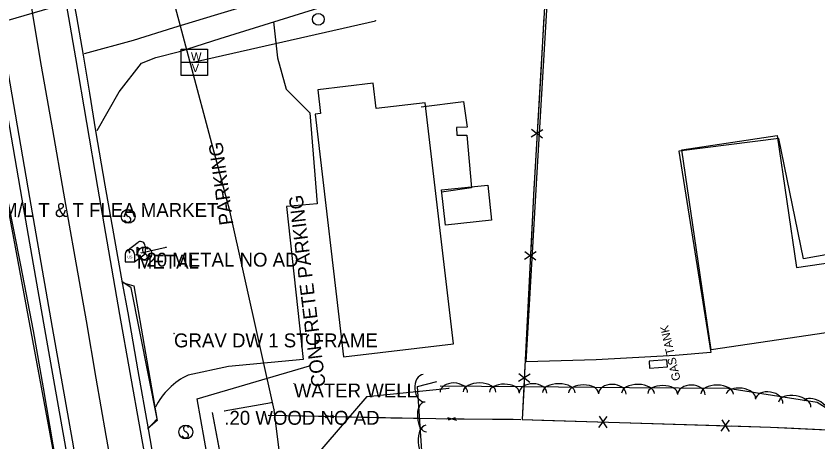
# Model space of a CAD drawing. Extents: x 954793 to 988390, y 1867850 to 1924428.
# Drawn here: x 961031.7 to 961319.6, y 1902915.2 to 1903068.1 of the extents above; entities that cross this region are included whole.
import ezdxf

# ---------------------------------------------------------------- set-up
doc = ezdxf.new("R2010")
doc.units = 0
for name, color, linetype in [('S_BUILDING', 7, 'Continuous'), ('S_DRIVEWAY', 7, 'Continuous'), ('S_EDGE_BITUMINOUS', 7, 'Continuous'), ('S_EDGE_PAVEMENT', 7, 'Continuous'), ('S_FENCE', 7, 'Continuous'), ('S_FIBER_OPTIC_CABLE', 7, 'Continuous'), ('S_MAILBOX', 7, 'Continuous'), ('S_MAILBOX_ANNOT', 7, 'Continuous'), ('S_MISC_STRUCTURES_ANNOT', 7, 'Continuous'), ('S_MSC_PT_SYM', 7, 'Continuous'), ('S_PARKING', 7, 'Continuous'), ('S_PARKING_ANNOT', 7, 'Continuous'), ('S_PAVEMENT_CROWN', 7, 'Continuous'), ('S_SHOULDER', 7, 'Continuous'), ('S_SIDEWALK', 7, 'Continuous'), ('S_SIGN', 7, 'Continuous'), ('S_SIGN_ANNOT', 7, 'Continuous'), ('S_SURVEY_TEXT_ANNOT', 7, 'Continuous'), ('S_TANK', 7, 'Continuous'), ('S_TANK_ANNOT', 7, 'Continuous'), ('S_TREE', 7, 'Continuous'), ('S_UTILITY_POLE', 7, 'Continuous'), ('S_UTL_PT_SYM', 7, 'Continuous'), ('S_WATER_UTILITIES', 7, 'Continuous')]:
    doc.layers.add(name, color=color, linetype=linetype)

msp = doc.modelspace()

# ---------------------------------------------------------------- linework, layer by layer
at = {"layer": 'S_BUILDING'}
for points in [[(961401.25, 1903053.87), (961415.21, 1902959.18), (961365.05, 1902951.78), (961363.77, 1902960.43), (961281.23, 1902948.25), (961270.63, 1903020.12), (961304.87, 1903025.17), (961311.86, 1902977.78), (961359.9, 1902984.86), (961350.93, 1903045.68), (961359.99, 1903047.01), (961357.21, 1903065.89), (961389.48, 1903070.65), (961392.15, 1903052.53)], [(961139.02, 1903032.84), (961149.25, 1902945.72), (961188.7, 1902950.35), (961178.53, 1903036.99), (961160.94, 1903034.93), (961159.87, 1903043.96), (961140, 1903041.62), (961141.01, 1903033.07)], [(961184.43, 1903005.66), (961201, 1903007.43), (961202.35, 1902994.79), (961185.78, 1902993.02)]]:
    msp.add_lwpolyline(points, close=True, dxfattribs=at)
at = {"layer": 'S_DRIVEWAY'}
msp.add_lwpolyline([(961078.83, 1902919.71), (961082.32, 1902923.43), (961073.02, 1902970.46), (961069.64, 1902972.84)], dxfattribs=at)
at = {"layer": 'S_EDGE_BITUMINOUS'}
msp.add_lwpolyline([(961069.82, 1902972.37), (961073.98, 1902971.18), (961078.17, 1902947.05), (961082.36, 1902922.92), (961079.02, 1902919.95)], dxfattribs=at)
at = {"layer": 'S_EDGE_PAVEMENT'}
for points in [[(961060.73, 1903027.01), (961068.72, 1903040.88), (961076.68, 1903051.15), (961081.87, 1903053.21), (961090.4, 1903055.36), (961104.93, 1903060.01), (961126.13, 1903066.6), (961147.32, 1903073.18), (961159.73, 1903077.37), (961172.15, 1903081.57), (961190.01, 1903086.88), (961207.87, 1903092.2), (961227.73, 1903098.15), (961247.58, 1903104.09), (961263.92, 1903109.2), (961280.27, 1903114.31), (961299.71, 1903120.85), (961319.15, 1903127.4)], [(961047.93, 1903081.96), (961050.48, 1903067.55), (961053.03, 1903053.14), (961056.95, 1903029.92), (961060.87, 1903006.7), (961064.86, 1902983.82), (961068.85, 1902960.94), (961072.54, 1902940.11), (961076.23, 1902919.29), (961078.72, 1902905.24), (961081.21, 1902891.2), (961083.69, 1902877.15), (961086.18, 1902863.11), (961090.17, 1902839.81), (961094.16, 1902816.52), (961096.49, 1902803.1), (961098.82, 1902789.68), (961101.15, 1902776.26), (961103.48, 1902762.84), (961107.47, 1902739.23)], [(961023.34, 1903078.83), (961026.09, 1903063.14), (961028.84, 1903047.45), (961032.65, 1903025.21), (961036.45, 1903002.97), (961040.53, 1902979.61), (961044.61, 1902956.25), (961048.19, 1902936.04), (961051.77, 1902915.83), (961054.24, 1902901.71), (961056.72, 1902887.6), (961059.19, 1902873.49), (961061.67, 1902859.37), (961065.88, 1902834.91), (961070.09, 1902810.45), (961072.32, 1902797.5), (961074.55, 1902784.54), (961076.78, 1902771.59), (961079.01, 1902758.64), (961083.19, 1902734.7)], [(961058.76, 1902858.83), (961053.44, 1902863.02), (961051.34, 1902875.79), (961049.24, 1902888.57), (961047.14, 1902901.34), (961045.04, 1902914.12), (961041.49, 1902934.57), (961037.94, 1902955.02), (961033.34, 1902978.62), (961028.75, 1903002.21), (961015.27, 1903016.73), (960998.81, 1903026.02), (960998.57, 1903026.21), (960998.26, 1903027.76), (960985.79, 1903028.87), (960970.72, 1903024.96), (960955.65, 1903021.05), (960935.33, 1903015.2), (960915, 1903009.35), (960893.77, 1903002.48), (960872.54, 1902995.61)]]:
    msp.add_lwpolyline(points, dxfattribs=at)
at = {"layer": 'S_FENCE'}
for p, q in [((961220.84, 1903027.29), (961216.58, 1903024.67)), ((961216.75, 1903027.53), (961220.67, 1903024.43)), ((961218.43, 1902983.39), (961214.2, 1902980.73)), ((961214.34, 1902983.59), (961218.29, 1902980.53)), ((961216.24, 1902939.49), (961212.01, 1902936.82)), ((961212.16, 1902939.69), (961216.1, 1902936.62)), ((961142.73, 1902924.8), (961145.65, 1902923.89)), ((961142.78, 1902923.95), (961145.59, 1902924.74)), ((961186.58, 1902923.92), (961189.74, 1902923.04)), ((961186.88, 1902923.07), (961189.44, 1902923.9)), ((961240.89, 1902920.33), (961243.89, 1902924.34)), ((961241.02, 1902924.43), (961243.76, 1902920.25)), ((961284.86, 1902919), (961287.85, 1902923)), ((961284.99, 1902923.09), (961287.72, 1902918.91))]:
    msp.add_line(p, q, dxfattribs=at)
for points in [[(961222.61, 1903091.86), (961217.4, 1903003.76), (961213.38, 1902923.22), (961302.52, 1902920.51), (961347.6, 1902918.37)], [(961221.19, 1903067.91), (961220.01, 1903047.94)], [(961220.01, 1903047.94), (961218.83, 1903027.97)], [(961218.59, 1903023.98), (961217.41, 1903004.02)], [(961217.41, 1903004.02), (961217.4, 1903003.76), (961216.42, 1902984.06)], [(961216.22, 1902980.07), (961215.22, 1902960.11)], [(961215.22, 1902960.11), (961214.23, 1902940.15)], [(961214.03, 1902936.16), (961213.38, 1902923.22), (961220.41, 1902923)], [(961102.07, 1902925.76), (961105.82, 1902906.12)], [(961102.07, 1902925.76), (961110.14, 1902883.53)], [(961122.19, 1902924.81), (961142.19, 1902924.38)], [(961122.19, 1902924.81), (961182.37, 1902923.53), (961212.83, 1902923.27)], [(961146.19, 1902924.3), (961166.18, 1902923.87)], [(961166.18, 1902923.87), (961182.37, 1902923.53), (961186.16, 1902923.5)], [(961190.15, 1902923.46), (961210.09, 1902923.29)], [(961210.09, 1902923.29), (961212.83, 1902923.27)], [(961220.41, 1902923), (961240.39, 1902922.4)], [(961244.39, 1902922.27), (961264.37, 1902921.67)], [(961264.37, 1902921.67), (961284.36, 1902921.06)], [(961288.35, 1902920.94), (961302.52, 1902920.51), (961308.33, 1902920.23)], [(961308.33, 1902920.23), (961328.3, 1902919.28)]]:
    msp.add_lwpolyline(points, dxfattribs=at)
at = {"layer": 'S_FIBER_OPTIC_CABLE'}
for p, q in [((961071.39, 1903079.05), (960949.84, 1903043.36)), ((961096.7, 1902930.63), (961136.96, 1902942.53)), ((961157.73, 1902931.5), (961187.1, 1902934.47)), ((961101.74, 1902902.43), (961096.7, 1902930.63)), ((961123.47, 1902891.73), (961157.73, 1902931.5))]:
    msp.add_line(p, q, dxfattribs=at)
at = {"layer": 'S_MAILBOX'}
for p, q in [((961071.41, 1902983.84), (961075.54, 1902986.95)), ((961075.03, 1902985.13), (961075.03, 1902982.42)), ((961077.98, 1902985.48), (961077.98, 1902982.76)), ((961070.86, 1902982.57), (961070.86, 1902979.85)), ((961074.18, 1902979.85), (961077.98, 1902982.76)), ((961074.18, 1902982.57), (961074.18, 1902979.85)), ((961070.86, 1902979.85), (961074.18, 1902979.85))]:
    msp.add_line(p, q, dxfattribs=at)
for points in [[(961072.04, 1902983.68), (961072.26, 1902983.54), (961072.26, 1902983.16), (961072.57, 1902983.16), (961072.57, 1902983.52), (961072.37, 1902983.77), (961072.04, 1902983.71)], [(961075.03, 1902985.13), (961076.13, 1902984.47), (961075.03, 1902984.12)]]:
    msp.add_lwpolyline(points, dxfattribs=at)
for centre, end in [((961076.31, 1902985.48), 117.5718), ((961072.52, 1902982.57), 180)]:
    msp.add_arc(centre, 1.66, 0, end, dxfattribs=at)
msp.add_ellipse((961075.03, 1902982.42), major_axis=(0.145, 0.132), ratio=0.564646, dxfattribs=at)
at = {"layer": 'S_MSC_PT_SYM'}
for points in [[(961085.5, 1902985.08), (961085.5, 1902985.13), (961085.5, 1902985.08), (961085.45, 1902985.08), (961085.5, 1902985.08), (961085.5, 1902985.03), (961085.5, 1902985.08), (961085.55, 1902985.08)], [(961076.59, 1902983.12), (961076.59, 1902983.17), (961076.59, 1902983.12), (961076.54, 1902983.12), (961076.59, 1902983.12), (961076.59, 1902983.07), (961076.59, 1902983.12), (961076.64, 1902983.12)], [(961088.38, 1902954.13), (961088.38, 1902954.18), (961088.38, 1902954.13), (961088.33, 1902954.13), (961088.38, 1902954.13), (961088.38, 1902954.08), (961088.38, 1902954.13), (961088.43, 1902954.13)], [(961131.39, 1902936.13), (961131.39, 1902936.18), (961131.39, 1902936.13), (961131.34, 1902936.13), (961131.39, 1902936.13), (961131.39, 1902936.08), (961131.39, 1902936.13), (961131.44, 1902936.13)], [(961123.38, 1902929.36), (961123.38, 1902929.41), (961123.38, 1902929.36), (961123.33, 1902929.36), (961123.38, 1902929.36), (961123.38, 1902929.31), (961123.38, 1902929.36), (961123.43, 1902929.36)], [(961106.42, 1902926.33), (961106.42, 1902926.38), (961106.42, 1902926.33), (961106.37, 1902926.33), (961106.42, 1902926.33), (961106.42, 1902926.28), (961106.42, 1902926.33), (961106.47, 1902926.33)]]:
    msp.add_lwpolyline(points, dxfattribs=at)
at = {"layer": 'S_PARKING'}
for points in [[(961442.59, 1903008.18), (961440.03, 1902987.43), (961414.54, 1902983.52), (961406.85, 1903034.4), (961422.08, 1903036.41), (961420.6, 1903054.73), (961394.77, 1903050.67), (961392.54, 1903068.96), (961357.51, 1903065.09), (961359.66, 1903046.21), (961351.14, 1903045.29), (961359.1, 1902988.92), (961314.38, 1902980.93), (961305.52, 1903024.11), (961269.61, 1903019.58), (961281.14, 1902947.29), (961268.3, 1902946.15), (961239.88, 1902944.69), (961214.76, 1902943.88), (961218.71, 1903011.95), (961223.31, 1903088.55), (961222.99, 1903096.25)], [(961124.06, 1903066.08), (961125.54, 1903053.15), (961128.69, 1903041.85), (961137.11, 1903033.4), (961139.74, 1903000.63), (961128.8, 1902999.67), (961134.79, 1902944.76), (961107.93, 1902942.24), (961093.47, 1902939.17)], [(961027.6, 1903005.14), (961048.52, 1902892.92), (961052.76, 1902863.01), (961058.83, 1902858.27)]]:
    msp.add_lwpolyline(points, dxfattribs=at)
msp.add_ellipse((961103.79, 1902916.93), major_axis=(-15.3, -19.17), ratio=0.999622, start_param=4.250093, end_param=4.933959, dxfattribs=at)
at = {"layer": 'S_PAVEMENT_CROWN'}
for points in [[(961056.23, 1903054.65), (961073.79, 1903059.49), (961088.34, 1903063.95), (961102.89, 1903068.4), (961123.67, 1903074.81), (961144.45, 1903081.22), (961157.27, 1903085.48), (961170.09, 1903089.74), (961187.27, 1903095.06), (961204.44, 1903100.37), (961224.65, 1903106.38), (961244.86, 1903112.39), (961261.53, 1903117.67), (961278.2, 1903122.94), (961297.67, 1903129.2), (961317.15, 1903135.46)], [(961056.23, 1903054.65), (961073.79, 1903059.49), (961088.34, 1903063.95), (961102.89, 1903068.4), (961123.67, 1903074.81), (961144.45, 1903081.22), (961157.27, 1903085.48), (961170.09, 1903089.74), (961187.27, 1903095.06), (961204.44, 1903100.37), (961224.65, 1903106.38), (961244.86, 1903112.39), (961261.53, 1903117.67), (961278.2, 1903122.94), (961297.67, 1903129.2), (961317.15, 1903135.46)], [(961035.75, 1903080.01), (961038.22, 1903065.09), (961040.69, 1903050.17), (961044.71, 1903027.31), (961048.73, 1903004.46), (961052.77, 1902981.55), (961056.81, 1902958.64), (961060.36, 1902938.04), (961063.9, 1902917.44), (961066.37, 1902903.42), (961068.83, 1902889.4), (961071.29, 1902875.38), (961073.76, 1902861.37), (961077.89, 1902837.27), (961082.02, 1902813.17), (961084.34, 1902800.09), (961086.66, 1902787), (961088.98, 1902773.92), (961091.3, 1902760.84), (961095.39, 1902737.14)], [(961035.75, 1903080.01), (961038.22, 1903065.09), (961040.69, 1903050.17), (961044.71, 1903027.31), (961048.73, 1903004.46), (961052.77, 1902981.55), (961056.81, 1902958.64), (961060.36, 1902938.04), (961063.9, 1902917.44), (961066.37, 1902903.42), (961068.83, 1902889.4), (961071.29, 1902875.38), (961073.76, 1902861.37), (961077.89, 1902837.27), (961082.02, 1902813.17), (961084.34, 1902800.09), (961086.66, 1902787), (961088.98, 1902773.92), (961091.3, 1902760.84), (961095.39, 1902737.14)]]:
    msp.add_lwpolyline(points, dxfattribs=at)
at = {"layer": 'S_SHOULDER'}
for points in [[(961020.37, 1903078.73), (961023.24, 1903062.82), (961026.1, 1903046.91), (961029.94, 1903024.65), (961033.79, 1903002.38), (961037.87, 1902979.06), (961041.94, 1902955.75), (961045.51, 1902935.45), (961049.08, 1902915.15), (961051.51, 1902901.08), (961053.93, 1902887.01), (961056.35, 1902872.94), (961058.77, 1902858.87), (961062.94, 1902834.53), (961067.1, 1902810.2), (961069.46, 1902797.13), (961071.81, 1902784.06), (961074.17, 1902770.99), (961076.52, 1902757.92), (961080.63, 1902734.07)], [(961050.91, 1903081.47), (961053.35, 1903067.79), (961055.79, 1903054.11), (961058, 1903040.48), (961060.22, 1903026.84), (961063.5, 1903007.34), (961066.66, 1902989.85), (961069.82, 1902972.36), (961071.75, 1902961.5), (961075.39, 1902940.7), (961079.04, 1902919.9), (961082.61, 1902899.75), (961086.19, 1902879.61), (961088.97, 1902862.22), (961093.21, 1902838.64), (961096.64, 1902817.03), (961098.98, 1902803.6), (961101.31, 1902790.16), (961103.65, 1902776.73), (961105.98, 1902763.29), (961110.19, 1902739.79)]]:
    msp.add_lwpolyline(points, dxfattribs=at)
at = {"layer": 'S_SIDEWALK'}
msp.add_lwpolyline([(961177.1, 1903035.57), (961192.36, 1903037.42), (961193.67, 1903028.24), (961189.79, 1903028.06), (961189.96, 1903025.32), (961193.52, 1903025.29), (961195.18, 1903006.38), (961184.43, 1903004.9)], dxfattribs=at)
at = {"layer": 'S_SIGN'}
for p, q in [((961076.59, 1902983.12), (961085.5, 1902985.08)), ((961106.42, 1902926.33), (961123.38, 1902929.36))]:
    msp.add_line(p, q, dxfattribs=at)
for centre in [(961071.91, 1902996.18), (961077.87, 1902982.79), (961092.61, 1902918.74)]:
    msp.add_circle(centre, 2.49, dxfattribs=at)
for centre, radius, start, end in [((961071.98, 1902997.45), 0.95, 16.5258, 156.8957), ((961072.59, 1902997.5), 1.5, 167.1196, 241.9813), ((961071.49, 1902994.84), 1.4, 358.6529, 73.7063), ((961071.75, 1902995.36), 1.28, 204.641, 335.359), ((961078.55, 1902984.11), 1.5, 167.1196, 241.9813), ((961077.94, 1902984.05), 0.95, 16.5258, 156.8957), ((961077.71, 1902981.96), 1.28, 204.641, 335.359), ((961077.45, 1902981.44), 1.4, 358.6529, 73.7063), ((961093.3, 1902920.07), 1.5, 167.1196, 241.9813), ((961092.69, 1902920.01), 0.95, 16.5258, 156.8957), ((961092.2, 1902917.4), 1.4, 358.6529, 73.7063), ((961092.46, 1902917.92), 1.28, 204.641, 335.359)]:
    msp.add_arc(centre, radius, start, end, dxfattribs=at)
at = {"layer": 'S_TANK'}
msp.add_lwpolyline([(961259.13, 1902941.67), (961265.49, 1902942.14), (961265.3, 1902944.7), (961258.94, 1902944.23)], close=True, dxfattribs=at)
at = {"layer": 'S_TREE'}
msp.add_lwpolyline([(961183.9, 1902935.37), (961213.59, 1902935.08), (961251.85, 1902934.75), (961287.23, 1902934.44), (961319.24, 1902929.42), (961339.5, 1902916.72), (961348, 1902878.82), (961348.06, 1902860.84), (961327.02, 1902859.93), (961309.93, 1902880.86), (961292.81, 1902901.66), (961256.27, 1902911.08), (961225.36, 1902906.65), (961201.51, 1902907.04), (961177.33, 1902911.94), (961175.76, 1902935.13), (961182.67, 1902936.84)], dxfattribs=at)
for centre, major_axis, ratio in [((961178.19, 1902934.45), (0.33, -4.94), 0.685311), ((961188.83, 1902932.94), (-4.96, 0.05), 0.685311), ((961198.09, 1902933.11), (-5.87, 0.06), 0.55008), ((961206.96, 1902933.02), (-5.35, 0.05), 0.540699), ((961217.26, 1902932.67), (-4.96, 0.04), 0.685311), ((961226.52, 1902932.85), (-5.87, 0.05), 0.55008), ((961235.39, 1902932.77), (-5.35, 0.05), 0.540699), ((961245.68, 1902932.42), (-4.96, 0.04), 0.685311), ((961254.95, 1902932.6), (-5.87, 0.05), 0.55008), ((961263.81, 1902932.53), (-5.35, 0.05), 0.540699), ((961274.11, 1902932.18), (-4.96, 0.04), 0.685311), ((961283.37, 1902932.36), (-5.87, 0.05), 0.55008), ((961291.87, 1902931.57), (-5.28, 0.83), 0.540699), ((961302, 1902929.71), (-4.9, 0.77), 0.685311), ((961311.19, 1902928.53), (-5.8, 0.91), 0.55008), ((961178.63, 1902924.15), (0.36, -5.33), 0.540699), ((961319.01, 1902927.06), (-4.53, 2.84), 0.540699), ((961179.23, 1902915.31), (0.4, -5.86), 0.55008)]:
    msp.add_ellipse(centre, major_axis=major_axis, ratio=ratio, start_param=3.141593, end_param=6.283185, dxfattribs=at)
at = {"layer": 'S_UTILITY_POLE'}
msp.add_circle((961140.18, 1903066.95), 2.13, dxfattribs=at)
at = {"layer": 'S_UTL_PT_SYM'}
for points in [[(961160.65, 1903066.43), (961160.65, 1903066.48), (961160.65, 1903066.43), (961160.6, 1903066.43), (961160.65, 1903066.43), (961160.65, 1903066.38), (961160.65, 1903066.43), (961160.7, 1903066.43)], [(961094.17, 1903051.37), (961094.17, 1903051.42), (961094.17, 1903051.37), (961094.12, 1903051.37), (961094.17, 1903051.37), (961094.17, 1903051.32), (961094.17, 1903051.37), (961094.22, 1903051.37)], [(961108.38, 1902998.12), (961108.38, 1902998.17), (961108.38, 1902998.12), (961108.33, 1902998.12), (961108.38, 1902998.12), (961108.38, 1902998.07), (961108.38, 1902998.12), (961108.43, 1902998.12)], [(961136.96, 1902942.53), (961136.96, 1902942.58), (961136.96, 1902942.53), (961136.91, 1902942.53), (961136.96, 1902942.53), (961136.96, 1902942.48), (961136.96, 1902942.53), (961137.01, 1902942.53)], [(961187.1, 1902934.47), (961187.1, 1902934.52), (961187.1, 1902934.47), (961187.05, 1902934.47), (961187.1, 1902934.47), (961187.1, 1902934.42), (961187.1, 1902934.47), (961187.15, 1902934.47)], [(961096.7, 1902930.63), (961096.7, 1902930.68), (961096.7, 1902930.63), (961096.65, 1902930.63), (961096.7, 1902930.63), (961096.7, 1902930.58), (961096.7, 1902930.63), (961096.75, 1902930.63)], [(961157.73, 1902931.5), (961157.73, 1902931.55), (961157.73, 1902931.5), (961157.68, 1902931.5), (961157.73, 1902931.5), (961157.73, 1902931.45), (961157.73, 1902931.5), (961157.78, 1902931.5)], [(961124.31, 1902926.65), (961124.31, 1902926.7), (961124.31, 1902926.65), (961124.26, 1902926.65), (961124.31, 1902926.65), (961124.31, 1902926.6), (961124.31, 1902926.65), (961124.36, 1902926.65)]]:
    msp.add_lwpolyline(points, dxfattribs=at)
at = {"layer": 'S_WATER_UTILITIES'}
for p, q in [((961108.38, 1902998.12), (961085.75, 1903082.92)), ((961094.17, 1903051.37), (961160.65, 1903066.43)), ((961090.92, 1903056.23), (961100.34, 1903056.23)), ((961090.92, 1903046.81), (961090.92, 1903056.23)), ((961100.34, 1903056.23), (961100.34, 1903046.81)), ((961090.92, 1903051.54), (961100.34, 1903051.54)), ((961100.34, 1903046.81), (961090.92, 1903046.81)), ((961124.31, 1902926.65), (961108.38, 1902998.12)), ((961135.91, 1902836.09), (961124.31, 1902926.65))]:
    msp.add_line(p, q, dxfattribs=at)

# ---------------------------------------------------------------- texts
at = {"layer": 'S_MAILBOX'}
msp.add_text('US', height=0.96, rotation=360, dxfattribs=at).set_placement((961071.62, 1902981.05))
at = {"layer": 'S_MAILBOX_ANNOT'}
msp.add_text('METAL', height=5, dxfattribs=at).set_placement((961075.03, 1902977.42))
at = {"layer": 'S_MISC_STRUCTURES_ANNOT'}
msp.add_text('WATER WELL', height=5, dxfattribs=at).set_placement((961131.39, 1902931.13))
at = {"layer": 'S_PARKING_ANNOT'}
for s, height, rotation, p in [('PARKING', 5, 97.6784, (961109.72, 1902993.38)), ('CONCRETE PARKING', 5.0004, 96.9139, (961142.86, 1902935.18))]:
    msp.add_text(s, height=height, rotation=rotation, dxfattribs=at).set_placement(p)
at = {"layer": 'S_SIGN_ANNOT'}
for s, p in [('3.00 P/M/L T & T FLEA MARKET', (961005.47, 1902995.95)), ('.20 METAL NO AD', (961076.59, 1902978.12)), ('.20 WOOD NO AD', (961106.42, 1902921.33))]:
    msp.add_text(s, height=5, dxfattribs=at).set_placement(p)
at = {"layer": 'S_SURVEY_TEXT_ANNOT'}
msp.add_text('GRAV DW 1 ST FRAME', height=5, dxfattribs=at).set_placement((961088.38, 1902949.13))
at = {"layer": 'S_TANK_ANNOT'}
msp.add_text('GAS TANK', height=3, rotation=102.852, dxfattribs=at).set_placement((961270.25, 1902937.49))
at = {"layer": 'S_WATER_UTILITIES'}
for s, p in [('W', (961094.47, 1903052.07)), ('V', (961094.71, 1903048.01))]:
    msp.add_text(s, height=3, rotation=360, dxfattribs=at).set_placement(p)

doc.saveas('drawing.dxf')
